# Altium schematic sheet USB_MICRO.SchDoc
size 297 x 209 mm
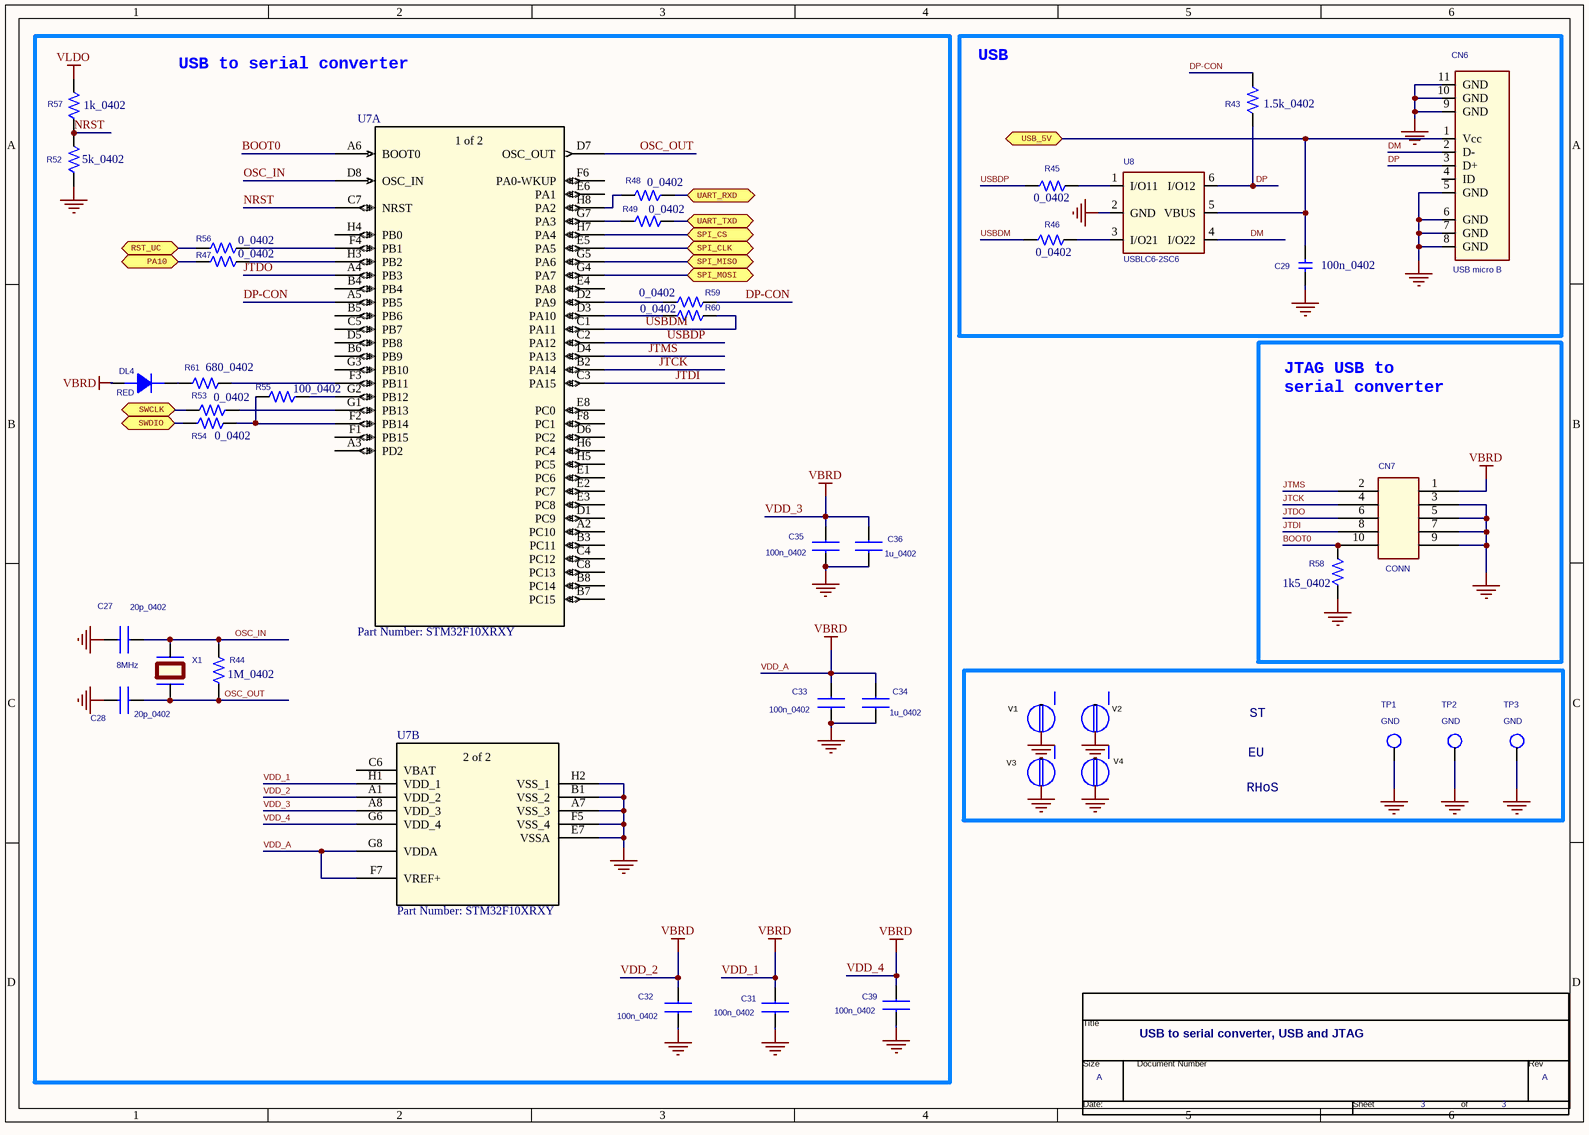
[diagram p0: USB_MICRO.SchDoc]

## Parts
*  Page Count: 3  Page Size: A  Title: USB to serial converter, USB and JTAG  (hidden comment: TitleBlock0)  (graphical)
C27  20p_0402  [0402_CAP_NP]
C28  20p_0402  [0402_CAP_NP]
C29  100n_0402  [0402_CAP_NP]
C31  100n_0402  [0402_CAP_NP]
C32  100n_0402  [0402_CAP_NP]
C33  100n_0402  [0402_CAP_NP]
C34  1u_0402  [0402_CAP_NP]
C35  100n_0402  [0402_CAP_NP]
C36  1u_0402  [0402_CAP_NP]
C39  100n_0402  [0402_CAP_NP]
CN6  USB micro B  [MICRO USB]
CN7  CONN  [AMPMODE10_50M]
DL4  RED  [SMD _LED]
R43  1.5k_0402  [0402_RESISTOR]
R44  1M_0402  [0402_RESISTOR]
R45  0_0402  [0402_RESISTOR]
R46  0_0402  [0402_RESISTOR]
R47  0_0402  [0402_RESISTOR]
R48  0_0402  [0402_RESISTOR]
R49  0_0402  [0402_RESISTOR]
R52  5k_0402  [0402_RESISTOR]
R53  0_0402  [0402_RESISTOR]
R54  0_0402  [0402_RESISTOR]
R55  100_0402  [0402_RESISTOR]
R56  0_0402  [0402_RESISTOR]
R57  1k_0402  [0402_RESISTOR]
R58  1k5_0402  [0402_RESISTOR]
R59  0_0402  [0402_RESISTOR]
R60  0_0402  [0402_RESISTOR]
R61  680_0402  [0402_RESISTOR]
ST1  stlogo  [stlogo]  (value not drawn)
ST2  EUlogo  [EU_ROHS_1_2]  (value not drawn)
ST3  RHoSlogo  [CH_ROHS_2]  (value not drawn)
TP1  GND  [TESTP]
TP2  GND  [TESTP]
TP3  GND  [TESTP]
U7  Part Number: STM32F10XRXY  [PCBComponent_1]  (parts A,B of 2)
U8  USBLC6-2SC6  [SOT23-6L_S]
V1  VITE  [FORO 3MM]  (value not drawn)
V2  VITE  [FORO 3MM]  (value not drawn)
V3  VITE  [FORO 3MM]  (value not drawn)
V4  VITE  [FORO 3MM]  (value not drawn)
X1  8MHz  [QUARZO]

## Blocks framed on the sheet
USB to serial converter: C27 C28 C31-C36 C39 DL4 R44 R47-R49 R52-R57 R59-R61 U7 X1
USB: C29 CN6 R43 R45 R46 U8

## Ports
PA10 (bidir), RST_UC (bidir), SPI_CLK (bidir), SPI_CS (bidir), SPI_MISO (bidir), SPI_MOSI (bidir), SWCLK (bidir), SWDIO (bidir), UART_RXD (bidir), UART_TXD (bidir), USB_5V (bidir)

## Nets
GND: C27.2 C28.2 C29.2 C31.1 C32.1 C33.1 C34.1 C35.1 C36.1 C39.1 CN6.5(GND) CN6.6(GND) CN6.7(GND) CN6.8(GND) CN6.9(GND) CN6.10(GND) CN6.11(GND) CN7.3(+) CN7.5(+) CN7.7(+) CN7.9(+) R52.1 R58.1 TP1.1(TP) TP2.1(TP) TP3.1(TP) U7.A7(VSS_3) U7.B1(VSS_2) U7.E7(VSSA) U7.F5(VSS_4) U7.H2(VSS_1) U8.2(GND) V1.1 V2.1 V3.1 V4.1
VDD_1: C31.2 C32.2 C33.2 C34.2 C35.2 C36.2 C39.2 CN7.1(+) DL4.1(ANODE) U7.A1(VDD_2) U7.A8(VDD_3) U7.F7(VREF+) U7.G6(VDD_4) U7.G8(VDDA) U7.H1(VDD_1)  [also labelled VBRD, VDD_2, VDD_3, VDD_4, VDD_A]
VLDO: R57.2
BOOT0: CN7.10(+) R58.2 U7.A6(BOOT0)
DM: CN6.2(D-) U8.4(I/O22)
DP: CN6.3(D+) R43.2 U8.6(I/O12)
DP-CON: R43.1 R59.2 U7.A5(PB5)
JTCK: CN7.4(+) U7.B2(PA14)
JTDI: CN7.8(+) U7.C3(PA15)
JTDO: CN7.6(+) U7.A4(PB3)
JTMS: CN7.2(+) U7.D4(PA13)
NRST: R52.2 R57.1 U7.C7(NRST)
OSC_IN: C27.1 R44.2 U7.D8(OSC_IN) X1.2
OSC_OUT: C28.1 R44.1 U7.D7(OSC_OUT) X1.1
PA10: R47.1 ; port PA10
RST_UC: R56.1 ; port RST_UC
SPI_CLK: U7.E5(PA5) ; port SPI_CLK
SPI_CS: U7.H7(PA4) ; port SPI_CS
SPI_MISO: U7.G5(PA6) ; port SPI_MISO
SPI_MOSI: U7.G4(PA7) ; port SPI_MOSI
SWCLK: R53.2 ; port SWCLK
SWDIO: R54.1 ; port SWDIO
UART_RXD: R48.1 ; port UART_RXD
UART_TXD: R49.2 ; port UART_TXD
USB_5V: C29.1 CN6.1(Vcc) U8.5(VBUS) ; port USB_5V
USBDM: R46.1 R60.2 U7.C1(PA11)
USBDP: R45.1 U7.C2(PA12)
NetDL4_2: DL4.2(CATHODE) R61.1
NetR45_2: R45.2 U8.1(I/O11)
NetR46_2: R46.2 U8.3(I/O21)
NetR47_2: R47.2 U7.H3(PB2)
NetR48_2: R48.2 U7.H8(PA2)
NetR49_1: R49.1 U7.G7(PA3)
NetR53_1: R53.1 U7.G1(PB13)
NetR54_2: R54.2 R55.2 U7.F2(PB14)
NetR55_1: R55.1 U7.G2(PB12)
NetR56_2: R56.2 U7.F4(PB1)
NetR59_1: R59.1 U7.D2(PA9)
NetR60_1: R60.1 U7.D3(PA10)
NetR61_2: R61.2 U7.F3(PB11)

Not connected (* = marked no-connect by the designer): CN6 4(ID); U7 A2(PC10) A3(PD2) B3(PC11) B4(PB4) B5(PB6) B6(PB9) B7(PC15) B8(PC14) C4(PC12) C5(PB7) C6(VBAT) C8(PC13) D1(PC9) D5(PB8) D6(PC2) E1(PC6) E2(PC7) E3(PC8) E4(PA8) E6(PA1) E8(PC0) F1(PB15) F6(PA0-WKUP) F8(PC1) G3(PB10) H4(PB0) H5(PC5) H6(PC4)

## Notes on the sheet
- JTAG USB to
  serial converter
- (near V1) V1
- (near V2) V2
- V3
- V4

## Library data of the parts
* = TitleBlock0: Doc: BLUENRG-2 APPLICATION BOARD
C27 C28 C31 C34 C36 C39 = MURATA GRM36: COMPHEIGHT: 0.000; MEMORY: NO; COMPGROUP: 0; COMPROT: 180; COMPLOC: [-1955.000,605.000]; COMPSIDE: TOP
C29 = C: PSpiceTemplate: C^@REFDES %1 %2 ?TOLERANCE¦C^@REFDES¦ @VALUE ?IC/IC=@IC/ ?TOLERANCE¦\n.model C^@REFDES CAP C=1 DEV=@TOLERANCE%¦; COMPHEIGHT: 0.000; MEMORY: NO; COMPGROUP: 0; COMPROT: 270; COMPLOC: [814.800,3196.200]; COMPSIDE: TOP
C32 C33 C35 = MURATA GRM36: COMPSIDE: TOP; COMPLOC: [-1955.000,605.000]; COMPROT: 180; COMPGROUP: 0; COMPFIXED: NO; COMPHEIGHT: 0.000
CN6 = USB micro B_0
CN7 = CON10AP
DL4 = Diodo_led: FPLIST: SM/D1206_S; COMPSIDE: TOP; COMPLOC: [1254.733,908.600]; COMPROT: 270; COMPGROUP: 0; COMPFIXED: NO; COMPHEIGHT: 0.000
R43 = R_Dup1: PSpiceTemplate: R^@REFDES %1 %2 ?TOLERANCE¦R^@REFDES¦ @VALUE  ?TOLERANCE¦\n.model R^@REFDES RES R=1 DEV=@TOLERANCE%¦; COMPHEIGHT: 0.000; MEMORY: NO; COMPGROUP: 0; COMPROT: 180; COMPLOC: [1050.667,2713.533]; COMPSIDE: TOP
R44 R45 = R_Dup1: PSpiceTemplate: R^@REFDES %1 %2 ?TOLERANCE¦R^@REFDES¦ @VALUE  ?TOLERANCE¦\n.model R^@REFDES RES R=1 DEV=@TOLERANCE%¦; COMPHEIGHT: 0.000; MEMORY: NO; COMPGROUP: 0; COMPROT: 180; COMPLOC: [1051.533,2790.267]; COMPSIDE: TOP
R46 R52 R57 R58 R60 R61 = R_Dup1: PSpiceTemplate: R^@REFDES %1 %2 ?TOLERANCE¦R^@REFDES¦ @VALUE  ?TOLERANCE¦\n.model R^@REFDES RES R=1 DEV=@TOLERANCE%¦; COMPHEIGHT: 0.000; MEMORY: NO; COMPGROUP: 0; COMPROT: 180; COMPLOC: [1219.333,2792.667]; COMPSIDE: TOP
R47-R49 R56 = R_Dup1: PSpiceTemplate: R^@REFDES %1 %2 ?TOLERANCE¦R^@REFDES¦ @VALUE  ?TOLERANCE¦\n.model R^@REFDES RES R=1 DEV=@TOLERANCE%¦
R53-R55 R59 = R_Dup1: PSpiceTemplate: R^@REFDES %1 %2 ?TOLERANCE¦R^@REFDES¦ @VALUE  ?TOLERANCE¦\n.model R^@REFDES RES R=1 DEV=@TOLERANCE%¦; COMPSIDE: TOP; COMPLOC: [1219.333,2792.667]; COMPROT: 180; COMPGROUP: 0; COMPFIXED: NO; COMPHEIGHT: 0.000
TP1 = T POINT R: COMPHEIGHT: 10.000; MEMORY: NO; COMPGROUP: 0; COMPROT: 270; COMPLOC: [1368.800,3252.867]; COMPSIDE: TOP
TP2 = T POINT R: COMPHEIGHT: 10.000; MEMORY: NO; COMPGROUP: 0; COMPROT: 270; COMPLOC: [3983.400,3545.533]; COMPSIDE: TOP
TP3 = T POINT R: COMPSIDE: TOP; COMPLOC: [734.867,493.467]; COMPROT: 270; COMPGROUP: 0; COMPFIXED: NO; COMPHEIGHT: 10.000
U7 = STM32F10XRXY: No Description Available; Vendor: STMicroelectronics
U8 = USBUFxxW6_0: COMPSIDE: TOP; COMPLOC: [940.933,3064.267]; COMPROT: 90; COMPGROUP: 0; COMPFIXED: NO; COMPHEIGHT: 0.000
V1 = VITE: COMPSIDE: TOP; COMPLOC: [3951.133,401.533]; COMPROT: 0; COMPFIXED: NO; COMPHEIGHT: 0.000
V2 = VITE: COMPSIDE: TOP; COMPLOC: [460.000,401.533]; COMPROT: 0; COMPFIXED: NO; COMPHEIGHT: 0.000
V3 = VITE: COMPSIDE: TOP; COMPLOC: [3942.867,4490.733]; COMPROT: 0; COMPFIXED: NO; COMPHEIGHT: 0.000
V4 = VITE: COMPSIDE: TOP; COMPLOC: [460.000,4504.667]; COMPROT: 0; COMPFIXED: NO; COMPHEIGHT: 0.000
X1 = QUARZO_Dup1: COMPSIDE: TOP; COMPLOC: [-4326.000,-12933.000]; COMPROT: 0; COMPFIXED: NO; COMPHEIGHT: 0.000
